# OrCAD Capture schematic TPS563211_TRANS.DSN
size D; title: TPS563211: 4.2-V to 18-V Input, 3-A Synchronous Buck; rev: 1.0; note: Datasheet: SLUSDX1     EVM: SLUUCC6; note: Synchronous Step Down Converter; note: Converter in SOT583 Package
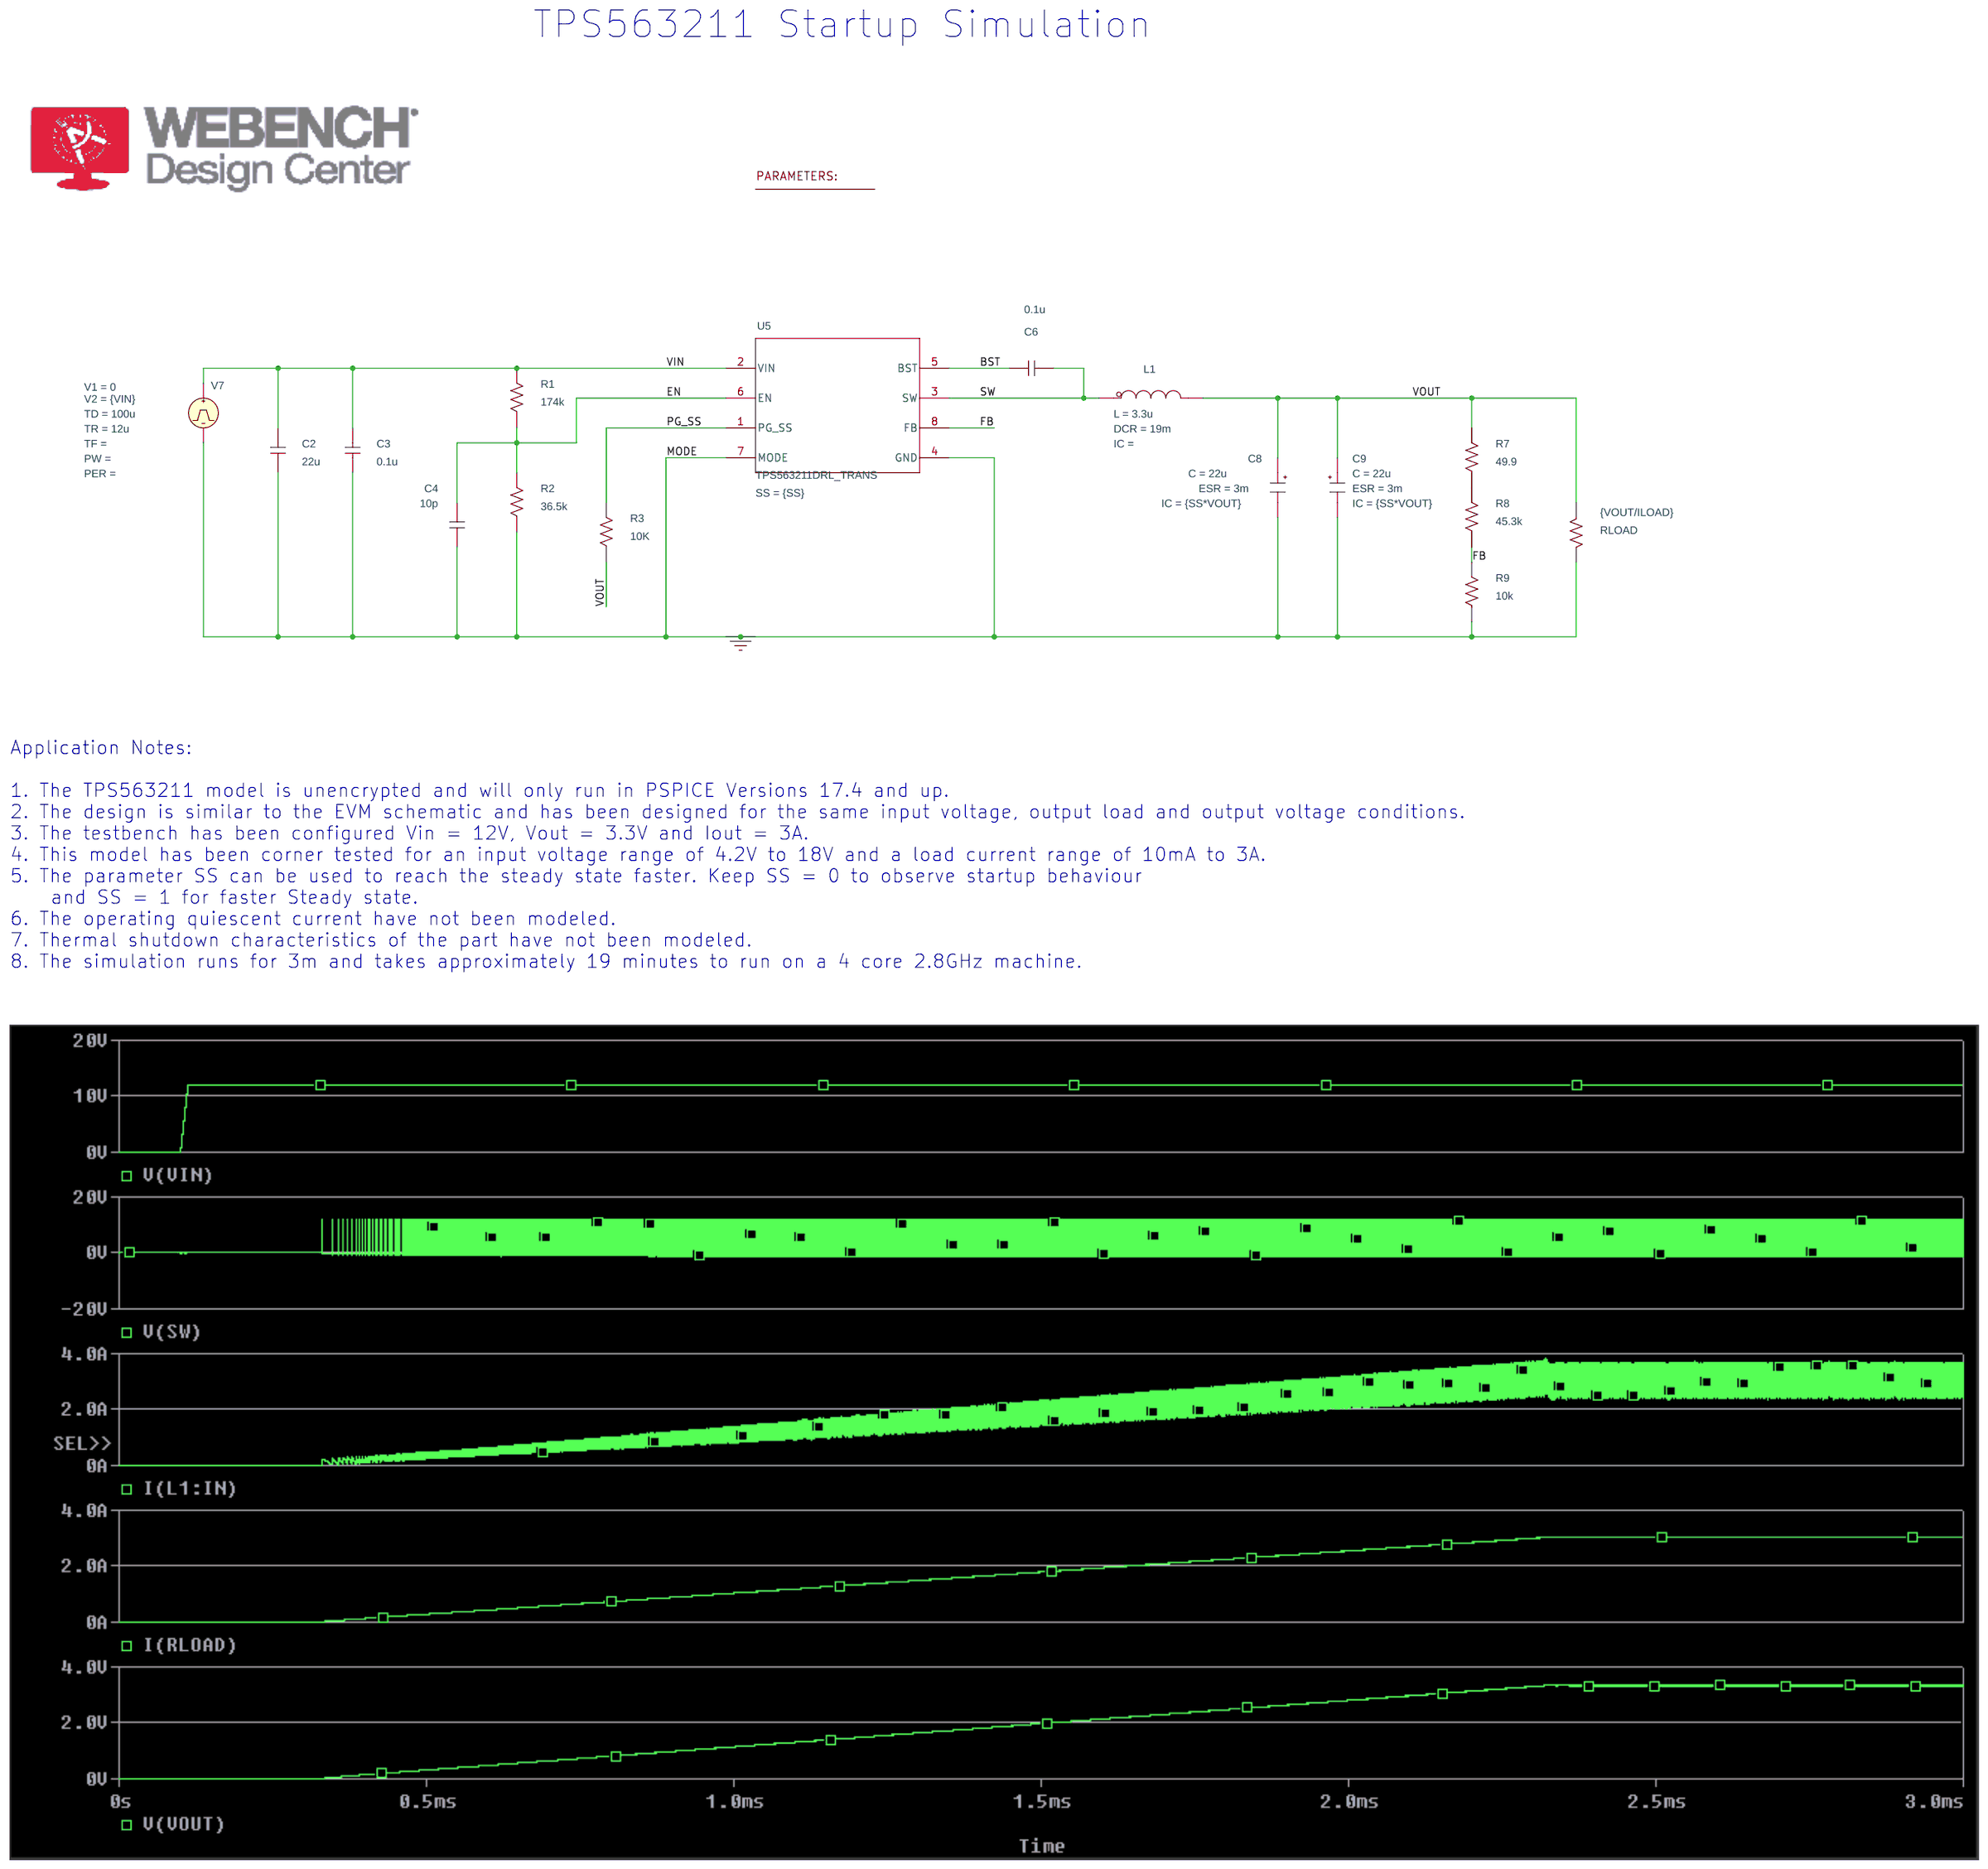
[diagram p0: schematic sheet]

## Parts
1  PARAM
C2  22u  [CK05]
C3  0.1u  [CK05]
C4  10p  [cap196]
C6  0.1u  [CK05]
C8  CESR
C9  CESR
L1  LDCR
R1  174k  [RC05]
R2  36.5k  [RC05]
R3  10K  [AXRC05]
R7  49.9  [RC05]
R8  45.3k  [RC05]
R9  10k  [RC05]
RLOAD  {VOUT/ILOAD}  [AXRC05]
U5  TPS563211DRL_TRANS  [DRL0008A-MFG]
V7  VPULSE

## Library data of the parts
1 = PARAM: ILOAD: 3; SS: 0; VIN: 12; VOUT: 3.3
C2-C4 C6 = C
C8 C9 = CESR_0: C: 22u; ESR: 3m; IC: {SS*VOUT}; PSpiceTemplate: X^@REFDES %IN %OUT @MODEL PARAMS:  ?C|C=@C||C=100u|  ?ESR|ESR=@ESR||ESR=0.01| ?X|X=@X||X=2|  ?IC|IC=@IC||IC=2|; X: 1
L1 = LDCR_1: DCR: 19m; L: 3.3u; PSpiceTemplate: X^@REFDES %IN %OUT @MODEL PARAMS:  ?L|L=@L||L=1u|  ?DCR|DCR=@DCR||DCR=0.01|  ?IC|IC=@IC||IC=0|
R1-R3 R7-R9 RLOAD = R
U5 = TPS563211DRL_TRANS: SS: {SS}
V7 = VPULSE: TD: 100u; TR: 12u; V1: 0; V2: {VIN}

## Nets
VIN: C2.2 C3.2 R1.2 U5.2(VIN) V7.1(+)
0: C2.1 C3.1 C4.1 C8.2(OUT) C9.2(OUT) R2.1 R9.1 RLOAD.2 U5.4(GND) U5.7(MODE) V7.2(-)
BST: C6.2 U5.5(BST)
EN: C4.2 R1.1 R2.2 U5.6(EN)
FB: R8.1 R9.2 U5.8(FB)
PG_SS: R3.2 U5.1(PG_SS)
SW: C6.1 L1.1(IN) U5.3(SW)
VOUT: C8.1(IN) C9.1(IN) L1.3(OUT) R3.1 R7.2 RLOAD.1
N16776452: R7.1 R8.2

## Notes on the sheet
- TPS563211 Startup Simulation
- Application Notes:
  1. The TPS563211 model is unencrypted and will only run in PSPICE Versions 17.4 and up.
  2. The design is similar to the EVM schematic and has been designed for the same input voltage, output load and output voltage conditions.
  3. The testbench has been configured Vin = 12V, Vout = 3.3V and Iout = 3A.
  4. This model has been corner tested for an input voltage range of 4.2V to 18V and a load current range of 10mA to 3A.
  5. The parameter SS can be used to reach the steady state faster. Keep SS = 0 to observe startup behaviour
      and SS = 1 for faster Steady state.
  6. The operating quiescent current have not been modeled.
  7. Thermal shutdown characteristics of the part have not been modeled.
  8. The simulation runs for 3m and takes approximately 19 minutes to run on a 4 core 2.8GHz machine.
